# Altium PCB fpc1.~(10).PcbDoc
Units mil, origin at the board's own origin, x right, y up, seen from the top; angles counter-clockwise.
Board outline 3634.73 x 289.23 mil, 2 copper layers (Top Layer, Bottom Layer), stack 1.929 mil thick; 4 components, 1 nets, 8 pads, 0 vias.
Unrouted connection lines stored in the file: 3.
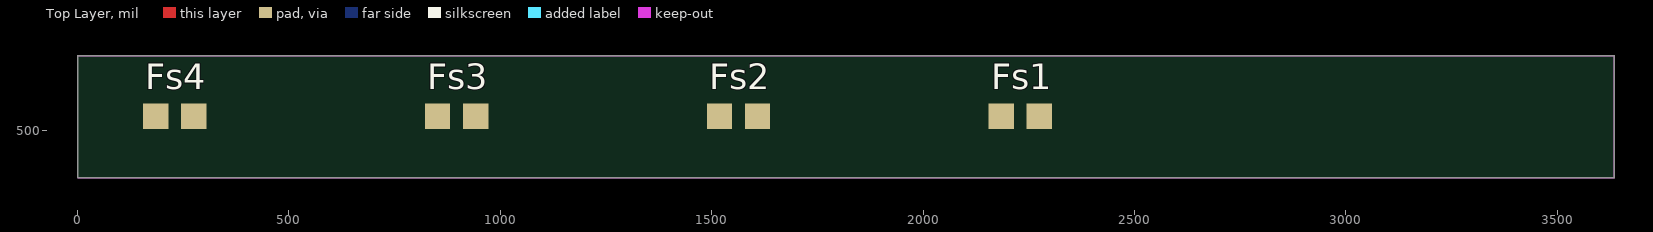
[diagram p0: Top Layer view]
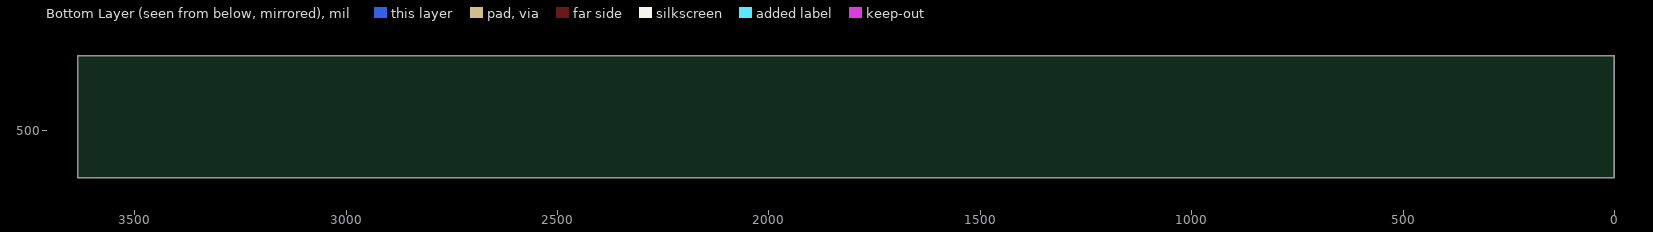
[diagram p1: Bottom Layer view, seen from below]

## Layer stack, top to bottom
Top Solder: solder mask 0.4, Solder Resist, Dk 3.5
Top Layer: signal copper 0.4724
Dielectric 1: dielectric 0.9843, FR-4, Dk 4.8
Bottom Layer: signal copper 0.4724
Bottom Solder: solder mask 0.4, Solder Resist, Dk 3.5

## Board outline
0.5,389.24 3634.7,389.24 3634.97,389.5 3634.97,678.2 3634.7,678.47 0.5,678.47 0.23,678.2

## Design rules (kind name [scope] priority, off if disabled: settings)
Clearance [All] p1: gap=10 ignorepadtopadclearanceinfootprint=FALSE except(0: Arc-Hole Track-Hole SMDPad-Hole THPad-Hole Via-Hole Fill-Hole Poly-Hole Region-Hole Text-Hole)
PolygonConnect [All] p1: connectstyle=Relief reliefconductorwidth=10 reliefentries=4 polygonreliefangle="90 Angle" airgapwidth=10
RoutingVias [All] p1: holewidth=28 width=50 viastyle="Through Hole" minholewidth=28 minwidth=50 maxholewidth=28 maxwidth=50
SolderMaskExpansion [All] p1: expansion=4 istentingtop=FALSE
Width [All] p1: maxlimit=10 minlimit=10 preferedwidth=10
30 further rules are at their usual default settings.

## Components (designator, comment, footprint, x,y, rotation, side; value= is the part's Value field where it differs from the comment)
Fs1 "ForceSensor" sensor_connector 2230,535 r0 top
Fs2 "ForceSensor" sensor_connector 1563.33,535 r0 top
Fs3 "ForceSensor" sensor_connector 896.67,535 r0 top
Fs4 "ForceSensor" sensor_connector 230,535 r0 top

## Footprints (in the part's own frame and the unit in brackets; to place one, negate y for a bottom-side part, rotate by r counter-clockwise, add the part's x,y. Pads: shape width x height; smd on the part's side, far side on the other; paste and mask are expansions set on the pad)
sensor_connector [mil]
  rect 60x60 smd: 1(-45,0) 2(45,0)

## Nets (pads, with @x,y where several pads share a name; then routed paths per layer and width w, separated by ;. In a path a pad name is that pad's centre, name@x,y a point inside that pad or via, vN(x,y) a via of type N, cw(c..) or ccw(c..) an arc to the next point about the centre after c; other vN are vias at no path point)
GND: Fs1.1 Fs2.1 Fs3.1 Fs4.1
pads on no net: Fs1.2 Fs2.2 Fs3.2 Fs4.2

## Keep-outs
Keep-Out Layer:
  lines w0.5: 0.5,389.5 0.5,678.2 3634.7,678.2 3634.7,389.5 0.5,389.5

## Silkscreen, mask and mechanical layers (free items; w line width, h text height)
Board Shape:
  lines w0.5: 0.5,389.5 0.5,678.2 3634.7,678.2 3634.7,389.5 0.5,389.5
